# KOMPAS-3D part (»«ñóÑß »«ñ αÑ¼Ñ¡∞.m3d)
File: created 26.10.2015 15:31:09, last saved 22.07.2016 14:57:03.
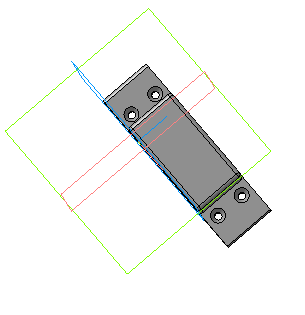
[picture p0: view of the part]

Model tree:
1. Эскиз:1
2. Операция выдавливания:1
     Расстояние 1 = 15
3. Эскиз:2
4. Вырезать элемент выдавливания:1
     Расстояние 1 = 20
5. Эскиз:3
6. Вырезать элемент выдавливания:2
     Расстояние 1 = 20
7. Эскиз:4
8. Вырезать элемент выдавливания:3
     Расстояние 1 = 3; Угол 1 = 27
9. Скругление:1
     Радиус = 1
10. Скругление:2
     Радиус = 1
11. Скругление:3
     Радиус = 1
12. Скругление:4
     Радиус = 1
13. Скругление:5
     Радиус = 1
14. Скругление:6
     Радиус = 1
15. Скругление:7
     Радиус = 1
16. Скругление:8
     Радиус = 1
17. Эскиз:5
18. Вырезать элемент выдавливания:4
     Расстояние 1 = 43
